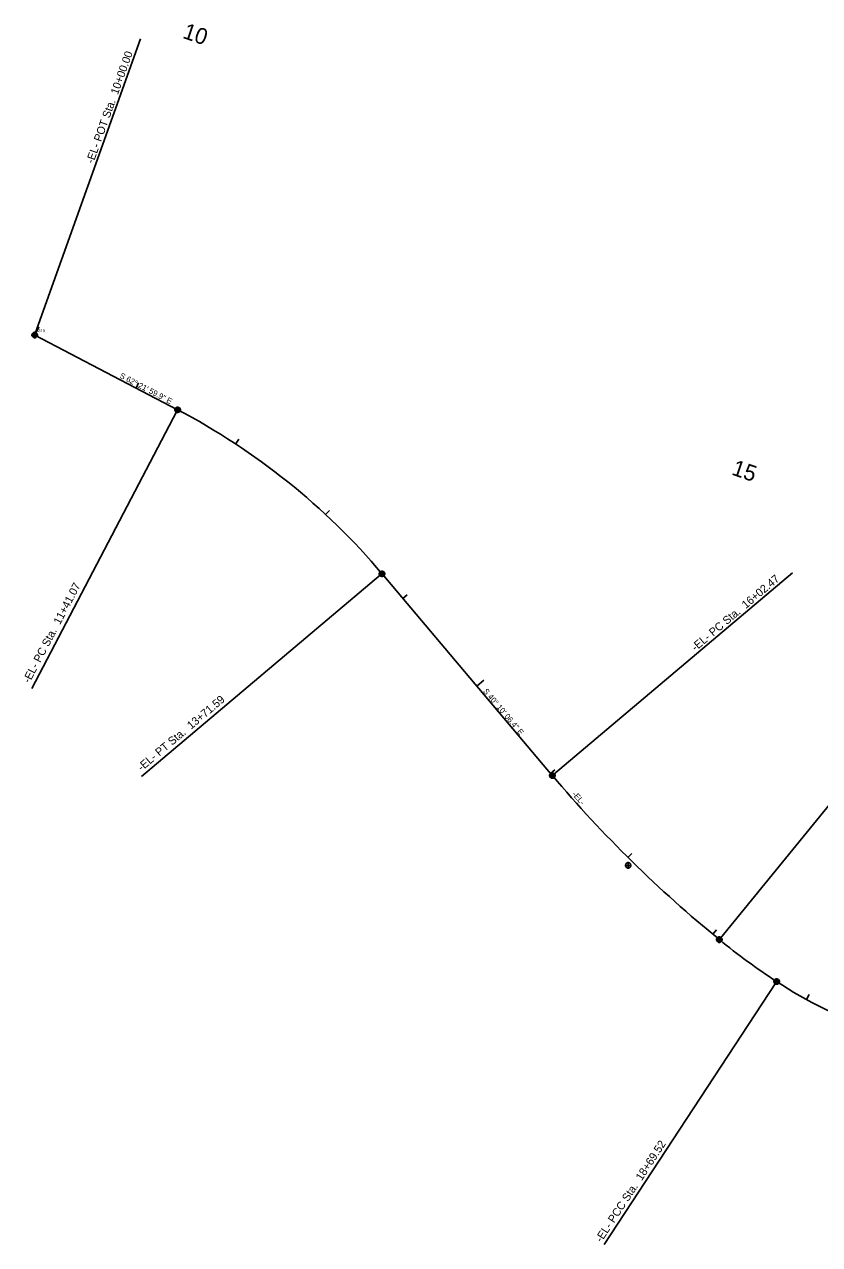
# Model space of a CAD drawing. Extents: x 928071 to 937324, y 684061 to 686812.
# Drawn here: x 928071 to 928766, y 685745 to 686812 of the extents above; entities that cross this region are included whole.
import ezdxf

# ---------------------------------------------------------------- set-up
doc = ezdxf.new("R2010")
doc.units = 0
for name, color, linetype in [('COGO Default Chain', 7, 'Continuous'), ('COGO Default Curve', 7, 'Continuous'), ('Cogo Default Point CELL', 7, 'Continuous'), ('COGO Default Point Number', 7, 'Continuous'), ('Default', 7, 'Continuous'), ('Exist Horizontal Alignment', 7, 'Continuous'), ('Exist Horizontal Alignment Direction Label', 7, 'Continuous'), ('Exist Horizontal Alignment Station Label', 7, 'Continuous'), ('Exist Horizontal Alignment Tick Label', 7, 'Continuous'), ('Exist Horizontal Alignment Tick Large', 7, 'Continuous'), ('Exist Horizontal Alignment Tick Small', 7, 'Continuous'), ('Prop DSN Text', 7, 'Continuous')]:
    doc.layers.add(name, color=color, linetype=linetype)

msp = doc.modelspace()

# ---------------------------------------------------------------- linework, layer by layer
at = {"layer": 'COGO Default Chain'}
for p, q in [((928080, 686540.2), (928205, 686474.8)), ((928383.7, 686331.4), (928532.6, 686155))]:
    msp.add_line(p, q, dxfattribs=at)
for centre, radius, start, end in [((927929, 685947.7), 595, 40.1684, 62.3666), ((929373.2, 686864.6), 1100, 220.1684, 230.8463), ((929057.5, 686476.8), 600, 230.8463, 236.7715), ((928947.9, 686309.5), 400, 236.7715, 263.987)]:
    msp.add_arc(centre, radius, start, end, dxfattribs=at)
at = {"layer": 'COGO Default Curve'}
for centre, radius, start, end in [((927929, 685947.7), 595, 40.1684, 62.3666), ((929373.2, 686864.6), 1100, 220.1684, 230.8463), ((929057.5, 686476.8), 600, 230.8463, 236.7715), ((928947.9, 686309.5), 400, 236.7715, 263.987)]:
    msp.add_arc(centre, radius, start, end, dxfattribs=at)
at = {"layer": 'Cogo Default Point CELL'}
for points in [[(928077, 686540.2), (928080, 686540.2)], [(928080, 686543.2), (928080, 686540.2)], [(928080, 686540.2), (928083, 686540.2)], [(928080, 686540.2), (928080, 686537.2)], [(928202, 686474.8), (928205, 686474.8)], [(928205, 686477.8), (928205, 686474.8)], [(928205, 686474.8), (928208, 686474.8)], [(928205, 686474.8), (928205, 686471.8)], [(928380.7, 686331.4), (928383.7, 686331.4)], [(928383.7, 686334.4), (928383.7, 686331.4)], [(928383.7, 686331.4), (928386.7, 686331.4)], [(928383.7, 686331.4), (928383.7, 686328.4)], [(928529.6, 686155), (928532.6, 686155)], [(928532.6, 686158), (928532.6, 686155)], [(928532.6, 686155), (928535.6, 686155)], [(928532.6, 686155), (928532.6, 686152)], [(928595.9, 686076.5), (928598.9, 686076.5)], [(928598.9, 686079.5), (928598.9, 686076.5)], [(928598.9, 686076.5), (928601.9, 686076.5)], [(928598.9, 686076.5), (928598.9, 686073.5)], [(928675.6, 686011.6), (928678.6, 686011.6)], [(928675.6, 686011.6), (928678.6, 686011.6)], [(928678.6, 686014.6), (928678.6, 686011.6)], [(928678.6, 686014.6), (928678.6, 686011.6)], [(928678.6, 686011.6), (928681.6, 686011.6)], [(928678.6, 686011.6), (928678.6, 686008.6)], [(928678.6, 686011.6), (928681.6, 686011.6)], [(928678.6, 686011.6), (928678.6, 686008.6)], [(928725.7, 685974.9), (928728.7, 685974.9)], [(928725.7, 685974.9), (928728.7, 685974.9)], [(928728.7, 685977.9), (928728.7, 685974.9)], [(928728.7, 685977.9), (928728.7, 685974.9)], [(928728.7, 685974.9), (928731.7, 685974.9)], [(928728.7, 685974.9), (928728.7, 685971.9)], [(928728.7, 685974.9), (928731.7, 685974.9)], [(928728.7, 685974.9), (928728.7, 685971.9)]]:
    msp.add_lwpolyline(points, dxfattribs=at)
for centre in [(928080, 686540.2), (928205, 686474.8), (928383.7, 686331.4), (928532.6, 686155), (928598.9, 686076.5), (928678.6, 686011.6), (928678.6, 686011.6), (928728.7, 685974.9), (928728.7, 685974.9)]:
    msp.add_circle(centre, 2.34, dxfattribs=at)
at = {"layer": 'Default'}
for p, q in [((928205, 686474.8), (928080, 686540.2)), ((928383.7, 686331.4), (928532.6, 686155))]:
    msp.add_line(p, q, dxfattribs=at)
for centre, radius, start, end in [((927929, 685947.7), 595, 40.1684, 62.3666), ((929373.2, 686864.6), 1100, 220.1684, 230.8463), ((929057.5, 686476.8), 600, 230.8463, 236.7715), ((928947.9, 686309.5), 400, 236.7715, 263.987)]:
    msp.add_arc(centre, radius, start, end, dxfattribs=at)
at = {"layer": 'Exist Horizontal Alignment'}
for p, q in [((928080, 686540.2), (928205, 686474.8)), ((928383.7, 686331.4), (928532.6, 686155))]:
    msp.add_line(p, q, dxfattribs=at)
for centre, radius, start, end in [((927929, 685947.7), 595, 40.1684, 62.3666), ((929373.2, 686864.6), 1100, 220.1684, 230.8463), ((929057.5, 686476.8), 600, 230.8463, 236.7715), ((928947.9, 686309.5), 400, 236.7715, 263.987)]:
    msp.add_arc(centre, radius, start, end, dxfattribs=at)
at = {"layer": 'Exist Horizontal Alignment Station Label'}
for p, q in [((928080.5, 686541.6), (928172.4, 686799.2)), ((928204.3, 686473.5), (928077.4, 686231.2)), ((928382.5, 686330.5), (928173.5, 686154.1)), ((928533.7, 686156), (928742.7, 686332.4)), ((928679.6, 686012.7), (928852.3, 686224.8)), ((928578, 685744.9), (928727.9, 685973.7))]:
    msp.add_line(p, q, dxfattribs=at)
for centre in [(928080, 686540.2), (928205, 686474.8), (928383.7, 686331.4), (928532.6, 686155), (928678.6, 686011.6), (928728.7, 685974.9)]:
    msp.add_circle(centre, 1.5, dxfattribs=at)
at = {"layer": 'Exist Horizontal Alignment Tick Large'}
for p, q in [((928080, 686540.2), (928083.7, 686547.3)), ((928466.5, 686233.3), (928472.6, 686238.5))]:
    msp.add_line(p, q, dxfattribs=at)
at = {"layer": 'Exist Horizontal Alignment Tick Small'}
for p, q in [((928168.6, 686493.8), (928170.9, 686498.3)), ((928255.7, 686444.9), (928258.5, 686449.1)), ((928334.3, 686383.2), (928337.7, 686386.9)), ((928402, 686309.7), (928405.8, 686313)), ((928531, 686156.9), (928534.8, 686160.1)), ((928598.7, 686083.4), (928602.2, 686086.9)), ((928672.8, 686016.3), (928676, 686020.2)), ((928754.8, 685959.2), (928757.2, 685963.6))]:
    msp.add_line(p, q, dxfattribs=at)

# ---------------------------------------------------------------- texts
at = {"layer": 'COGO Default Point Number'}
msp.add_text('G10', height=2.5, dxfattribs=at).set_placement((928082.5, 686542.7))
at = {"layer": 'Exist Horizontal Alignment Direction Label'}
msp.add_text('S 62%%d 21\' 59.9" E', height=5, rotation=332.3666, dxfattribs=at).set_placement((928153.8, 686503))
at = {"layer": 'Exist Horizontal Alignment Station Label'}
for s, rotation, p in [('-EL- POT Sta.  10+00.00', 70.3559, (928131.2, 686689.6)), ('-EL- PC Sta.  16+02.47', 40.1684, (928657.7, 686263.3)), ('-EL- PC Sta.  11+41.07', 62.3666, (928075.4, 686235.3)), ('-EL- PT Sta.  13+71.59', 40.1684, (928173.5, 686158.5)), ('-EL- PCC Sta.  18+69.52', 56.7715, (928575.4, 685746.3))]:
    msp.add_text(s, height=7, rotation=rotation, dxfattribs=at).set_placement(p)
at = {"layer": 'Exist Horizontal Alignment Tick Label'}
for s, p in [('10', (928208.6, 686800.1)), ('15', (928688.6, 686418.3))]:
    msp.add_text(s, height=14, rotation=341.1836, dxfattribs=at).set_placement(p)
at = {"layer": 'Prop DSN Text'}
for s, rotation, p in [('S 40%%d 10\' 06.4" E', 310.1684, (928471.7, 686228.5)), ('-EL-', 310.6341, (928549.6, 686138.5))]:
    msp.add_text(s, height=5, rotation=rotation, dxfattribs=at).set_placement(p)

doc.saveas('drawing.dxf')
